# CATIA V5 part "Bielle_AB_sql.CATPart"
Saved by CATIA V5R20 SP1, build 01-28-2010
Part number: Bielle AB sql
Publications: "B", "Droite.1", "Droite.2", "Droite.3", "AB"
Bounding box of the stored display mesh (mm): x -20 to 20, y 0 to 0, z 0 to 10
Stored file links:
  C:\Documents and Settings\pschann\Bureau\IAO\Bielle_AB_sql.CATPart
  J:\Projet\CAO\Projet IAO.CATProduct
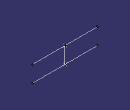
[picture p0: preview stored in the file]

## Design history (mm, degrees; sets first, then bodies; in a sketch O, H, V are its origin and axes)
Parameters
  AB = 10 mm
Set1
  Point1 "B": type OnPlane, Support yz-plane, H 0, V 10 {= AB}, Direction (0, 1, 0)
  Line1: type Normal, RefPoint Point1, RefSkin yz-plane, Start -20, End 20
  Line2: type PtPt, FirstPoint Point2, SecondPoint Point1
  Line3: type Normal, RefPoint Point2, RefSkin yz-plane, Start -20, End 20
  Point2 "Ap": type OnPlane, Support yz-plane, H 0, V 0, Direction (0, 1, 0)
Body1 (main body)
